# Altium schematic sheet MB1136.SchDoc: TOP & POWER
size A4; DocumentNumber: MB1136; Revision: C.3; SheetNumber: 1; SheetTotal: 4; Project: NUCLEO-XXXXRX
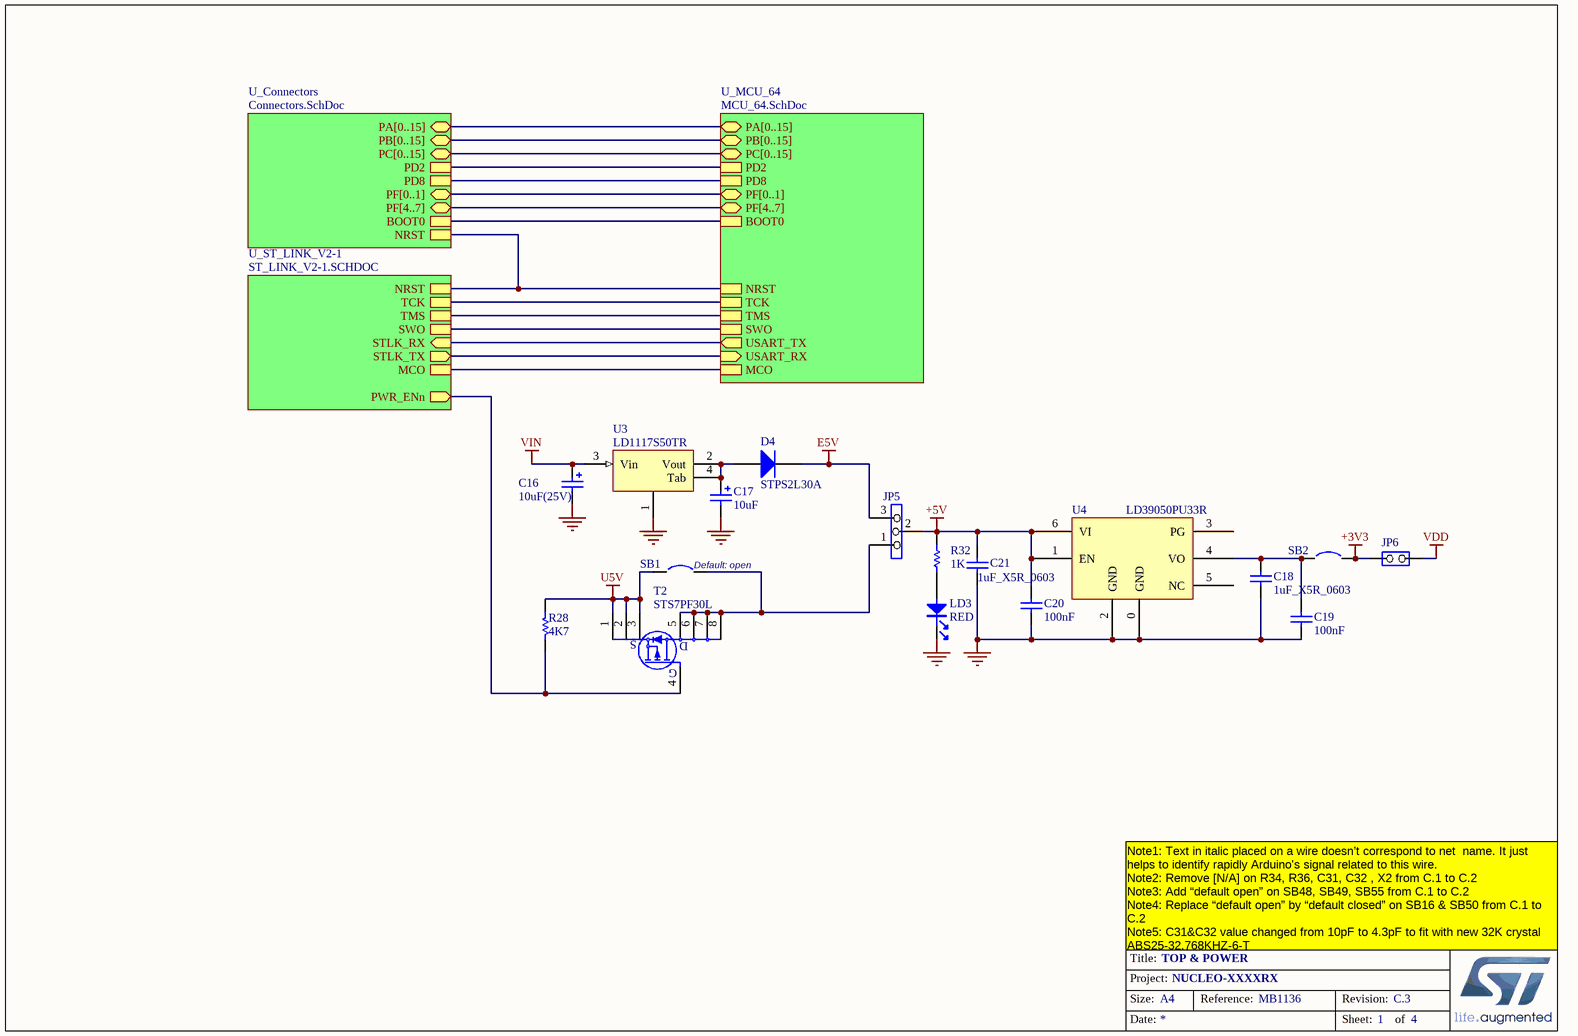
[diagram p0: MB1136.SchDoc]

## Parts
C16  10uF(25V)  [TAN-B]
C17  10uF  [TAN-A]
C18  1uF_X5R_0603  [0603C]
C19  100nF  [0603C]
C20  100nF  [0603C]
C21  1uF_X5R_0603  [0603C]
D4  STPS2L30A  [SMA]
JP5  (no value)  [SIP3]
JP6  (no value)  [SIP2/2.54]
LD3  RED  [0603D]
R28  4K7  [0603R]
R32  1K  [0603R]
SB1  Circuit Breaker  [JP2_SMD]  (value not drawn)
SB2  Circuit Breaker  [JP2_SMD]  (value not drawn)
T2  STS7PF30L  [SO8]
U3  LD1117S50TR  [SOT-223]
U4  LD39050PU33R  [DFN6(3X3)]

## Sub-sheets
U_Connectors = Connectors.SchDoc: PA[0..15] (bidir), PB[0..15] (bidir), PC[0..15] (bidir), PF[4..7] (bidir), PD2, PD8, PF[0..1] (bidir), NRST, BOOT0
U_MCU_64 = MCU_64.SchDoc: NRST, MCO, USART_RX (in), USART_TX (out), PA[0..15] (bidir), PB[0..15] (bidir), PC[0..15] (bidir), PF[4..7] (bidir), PD2, TCK, TMS, SWO, PD8, PF[0..1] (bidir), BOOT0
U_ST_LINK_V2-1 = ST_LINK_V2-1.SCHDOC: TMS, TCK, MCO, NRST, STLK_RX (in), STLK_TX (out), SWO, PWR_ENn (out)

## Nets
+3V3: JP6.1(COMMON) SB2.2
+5V: C20.2 C21.1 JP5.2 R32.2 U4.1(EN) U4.6(VI)
E5V: D4.2(K) JP5.3
GND: C16.2 C17.2 C18.2 C19.1 C20.1 C21.2 LD3.2 U3.1 U4.0(GND) U4.2(GND)
U5V: R28.1 SB1.1 T2.1(S) T2.2(S) T2.3(S)
VDD: JP6.2(NO)
VIN: C16.1 U3.3(Vin)
NetC17_1: C17.1 D4.1(A) U3.2(Vout) U3.4(Tab)
NetC18_1: C18.1 C19.2 SB2.1 U4.4(VO)
NetJP5_1: JP5.1 SB1.2 T2.5(D) T2.6(D) T2.7(D) T2.8(D)
NetLD3_1: LD3.1 R32.1
NetR28_2: R28.2 T2.4(G) ; sheet U_ST_LINK_V2-1/PWR_ENn
(unnamed): sheet U_ST_LINK_V2-1/TMS, sheet U_MCU_64/TMS
(unnamed): sheet U_ST_LINK_V2-1/TCK, sheet U_MCU_64/TCK  [a separate net that carries the same name]
(unnamed): sheet U_ST_LINK_V2-1/MCO, sheet U_MCU_64/MCO  [a separate net that carries the same name]
(unnamed): sheet U_ST_LINK_V2-1/NRST, sheet U_Connectors/NRST, sheet U_MCU_64/NRST  [a separate net that carries the same name]
(unnamed): sheet U_ST_LINK_V2-1/STLK_RX, sheet U_MCU_64/USART_TX  [a separate net that carries the same name]
(unnamed): sheet U_ST_LINK_V2-1/STLK_TX, sheet U_MCU_64/USART_RX  [a separate net that carries the same name]
(unnamed): sheet U_ST_LINK_V2-1/SWO, sheet U_MCU_64/SWO  [a separate net that carries the same name]
(unnamed): sheet U_Connectors/PD2, sheet U_MCU_64/PD2  [a separate net that carries the same name]
(unnamed): sheet U_Connectors/PD8, sheet U_MCU_64/PD8  [a separate net that carries the same name]
(unnamed): sheet U_Connectors/BOOT0, sheet U_MCU_64/BOOT0  [a separate net that carries the same name]

Not connected (* = marked no-connect by the designer): U4 3(PG) 5(NC)

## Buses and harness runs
bus sheet U_Connectors/PA[0..15] = sheet U_MCU_64/PA[0..15]
bus sheet U_Connectors/PB[0..15] = sheet U_MCU_64/PB[0..15]
bus sheet U_Connectors/PC[0..15] = sheet U_MCU_64/PC[0..15]
bus sheet U_Connectors/PF[0..1] = sheet U_MCU_64/PF[0..1]
bus sheet U_Connectors/PF[4..7] = sheet U_MCU_64/PF[4..7]

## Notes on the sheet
- (near SB1) Default: open
- Note1: Text in italic placed on a wire doesn’t correspond to net  name. It just helps to identify rapidly Arduino's signal related to this wire.
  Note2: Remove [N/A] on R34, R36, C31, C32 , X2 from C.1 to C.2
  Note3: Add “default open” on SB48, SB49, SB55 from C.1 to C.2
  Note4: Replace “default open” by “default closed” on SB16 & SB50 from C.1 to C.2
  Note5: C31&C32 value changed from 10pF to 4.3pF to fit with new 32K crystal ABS25-32.768KHZ-6-T
  Note5: C26's value changed from 2.2uF to 4.7uF from C.2 to C.3

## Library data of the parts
C16 C17 = Cap Pol1: Polarized Capacitor (Radial)
C18 C21 = CAP SMD 0603  X5R 1µF 25V 10%: 0603  X5R 1µF; Rated voltage: 25V; Tolerance: 10%
C19 C20 = Capacitor_ST: Capacitor 0402 / 0603 / 0805
D4 = STPS2L30A: Manuf_1: STM; Provided: ST; Order: BAT60JFILM; ECCN_US/EU: EAR99/NEC
JP5 = Jumper3
JP6 = JP2
LD3 = PHOTO
R28 = Res1: Resistor; Value: 1K
R32 = Resistor_ST: Resistor 0402 / 0603 / 0805; Description: Resistor 0402 or 0603 or 0805; Value: 10K
SB1 SB2 = Circuit Breaker: Solder: NO
U3 = LD1117
U4 = LD39050P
